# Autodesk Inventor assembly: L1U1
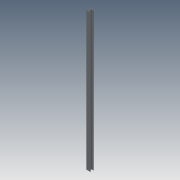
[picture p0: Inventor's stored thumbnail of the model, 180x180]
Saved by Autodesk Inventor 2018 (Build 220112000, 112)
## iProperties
Created: 2018-02
Part Number: L1U1
Document SubType Name: Assembly
Designer: STK
Author: STK
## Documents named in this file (3)
- D:\SolidWorks\Through Truss\L1U1\L1U1.iam
- D:\SolidWorks\Through Truss\L1U1\Web L1U1.ipt
- D:\SolidWorks\Through Truss\L1U1\Angle_L1U1.ipt
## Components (5 placed, 2 different names)
1. Web L1U1:1 — Mate:1, Mate:2, Flush:1, Mate:3, Flush:2, Flush:3
2. Angle_L1U1:1 — Mate:3, Flush:2, Flush:3
3. Angle_L1U1:2
4. Angle_L1U1:3
5. Angle_L1U1:4
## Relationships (6: Mate 3, Flush 3)
- Mate:1: Web L1U1:1
- Mate:2: Web L1U1:1
- Flush:1: Web L1U1:1
- Mate:3: Web L1U1:1 ↔ Angle_L1U1:1
- Flush:2: Web L1U1:1 ↔ Angle_L1U1:1
- Flush:3: Web L1U1:1 ↔ Angle_L1U1:1
